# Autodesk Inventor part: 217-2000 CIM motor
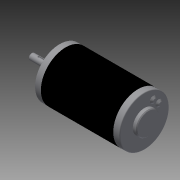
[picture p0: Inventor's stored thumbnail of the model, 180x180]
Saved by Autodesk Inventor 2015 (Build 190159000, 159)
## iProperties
Created: 2013-12
Part Number: 217-2000 CIM motor
Material: Generic
Document SubType Name: Modeling
Designer: Mech
Density: 3.57188 g/cm^3
Appearance: Default
Mass: 1279.13 g
Surface Area: 301.303 cm^2
Volume: 358.112 cm^3
Title: 217-2000.STEP
Description: STEP AP203
Creation Date: 2013-01-15
Sending System: SolidWorks 2012
Preprocessor: SwSTEP 2.0
Author: Mech
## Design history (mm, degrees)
node "217-20001"
node "Chamfer3"
node "Base1"
